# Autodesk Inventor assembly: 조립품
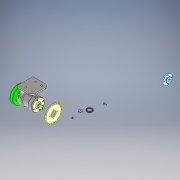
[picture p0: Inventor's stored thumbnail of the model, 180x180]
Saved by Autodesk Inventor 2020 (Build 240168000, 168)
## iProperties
Created: 2024-02
Part Number: 조립품
Document SubType Name: Assembly
Designer: oem
Author: oem
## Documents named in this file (18)
- C:\Users\oem\Desktop\740204V1003\조립품.iam
- C:\Users\oem\Desktop\740204V1003\V-벨트풀리.ipt
- C:\Users\oem\Desktop\740204V1003\가스켓.ipt
- C:\Users\oem\Desktop\740204V1003\깊은 홈 볼 베어링 6204.ipt
- C:\Users\oem\Desktop\740204V1003\본체.ipt
- C:\Users\oem\Desktop\740204V1003\스프로킷.ipt
- C:\Users\oem\Desktop\740204V1003\스프링 와셔 M5.ipt
- C:\Users\oem\Desktop\740204V1003\스프링 와셔 M10.ipt
- C:\Users\oem\Desktop\740204V1003\앤드 캡.ipt
- C:\Users\oem\Desktop\740204V1003\오일 실 20 32 5.ipt
- C:\Users\oem\Desktop\740204V1003\육각 너트 M10x1.ipt
- C:\Users\oem\Desktop\740204V1003\육각 소켓 머리 볼트 M4 x 10.ipt
- C:\Users\oem\Desktop\740204V1003\육각 소켓 머리 볼트 M5 x 12.ipt
- C:\Users\oem\Desktop\740204V1003\축.ipt
- C:\Users\oem\Desktop\740204V1003\커버.ipt
- C:\Users\oem\Desktop\740204V1003\평와셔 M10.ipt
- C:\Users\oem\Desktop\740204V1003\평행 키 5x5x12.ipt
- C:\Users\oem\Desktop\740204V1003\플랜지.ipt
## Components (4 placed, 3 different names)
1. V-벨트풀리:1 — 각도:1
2. 가스켓:1
3. 플랜지:1
4. 가스켓:2
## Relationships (1: Angle 1)
- 각도:1 [Angle]: V-벨트풀리:1
## Named parameters: d34_d32 = 0, d35_d16 = 0, d36_d17 = 0, d37_d18 = 0, d38_d19 = 0, d39_d20 = 0, d40_d21 = 0, d41_d22 = 0, d42_d23 = 0
